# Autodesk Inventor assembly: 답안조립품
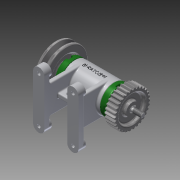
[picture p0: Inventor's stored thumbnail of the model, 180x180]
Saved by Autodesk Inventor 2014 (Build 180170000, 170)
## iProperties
Created: 2015-11
Part Number: 답안조립품
Document SubType Name: Assembly
Designer: Owner
Author: Owner
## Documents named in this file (9)
- C:\Documents and Settings\Owner\바탕 화면\451109V1002\451109V1002\답안조립품.iam
- C:\Documents and Settings\Owner\바탕 화면\451109V1002\451109V1002\본체.ipt
- C:\Documents and Settings\Owner\바탕 화면\451109V1002\451109V1002\축.ipt
- C:\Documents and Settings\Owner\바탕 화면\451109V1002\451109V1002\커버.ipt
- C:\Documents and Settings\Owner\바탕 화면\451109V1002\451109V1002\베어링 15 x 32 x 9.ipt
- C:\Documents and Settings\Owner\바탕 화면\451109V1002\451109V1002\오일 실 15 25 7.ipt
- C:\Documents and Settings\Owner\바탕 화면\451109V1002\451109V1002\V벨트풀리.ipt
- C:\Documents and Settings\Owner\바탕 화면\451109V1002\451109V1002\스퍼기어.ipt
- C:\Documents and Settings\Owner\바탕 화면\451109V1002\451109V1002\키 3 x 3 x 12.ipt
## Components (3 placed, 2 different names)
1. KS B 2023 6002 - 15 x 32 x 9:1
2. KS B 2023 6002 - 15 x 32 x 9:2
3. V벨트풀리:1
